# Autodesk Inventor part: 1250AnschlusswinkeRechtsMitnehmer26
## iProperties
Category: PARTsolutions
Created: 2011-08
Part Number: 1250AnschlusswinkeRechtsMitnehmer26
Catalog Web Link: www.cadenas.de
Description: 1250 Anschlusswinkel rechts Mitnehmer - Anschlusswinkel rechts Mitnehmer
Document SubType Name: Modeling
Designer: PARTsolutions
Density: 1 g/cm^3
Mass: 94.6561 g
Surface Area: 415.473 cm^2
Volume: 94.6561 cm^3
NB: 1250AnschlusswinkeRechtsMitnehmer26
NN: 1250 Anschlusswinkel rechts Mitnehmer
NT: Anschlusswinkel rechts Mitnehmer
NBSYN: 1250AnschlusswinkeRechtsMitnehmer26
LINA: 1250AnschlusswinkeRechtsMitnehmer26
BEST: 1250AnschlusswinkeRechtsMitnehmer
MA: 2
STEGV: 6
PIN: 18.800
KT: DUMMY
SUPPLIER: Kabelschlepp
ARTICLENO: 1250AnschlusswinkeRechtsMitnehmer26
BOMINFO: 1250AnschlusswinkeRechtsMitnehmer26
CREATOR: CADENAS GmbH
PSOL_IDENT_0: {\\10.0.0.251\ps_data\23d-libs\kabelschlepp\4_eketten_st\parts\1250_anschlusswinkel_rechts_m.prj},25
PSOL_IDENT_1: 1 {VTYP=3D},{NB=1250AnschlusswinkeRechtsMitnehmer26},{LINA=1250AnschlusswinkeRechtsMitnehmer26},{NN=
PSOL_IDENT_2: 1250 Anschlusswinkel rechts Mitnehmer},{DATE=31.05.2007 07:52:20},{GEOMDATE=20.03.2007 12:58:00},{VE
PSOL_IDENT_3: RSION=},{LINEID=10},{LINESUBID=-1},{WBVAR=MA,STEGV}  {NB=1250AnschlusswinkeRechtsMitnehmer26},{LINA=
PSOL_IDENT_4: 1250AnschlusswinkeRechtsMitnehmer26},{KT=DUMMY},{BEST=1250AnschlusswinkeRechtsMitnehmer},{MA=2},{STE
PSOL_IDENT_5: GV=6},{PIN=18.8}
Title: 1250AnschlusswinkeRechtsMitnehmer26
Author: Cadenas PARTsolutions
Comments: Anschlusswinkel rechts Mitnehmer
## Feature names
1. Extrusion1
2. Extrusion2
3. Extrusion3
4. Extrusion4
5. Extrusion5
6. Revolution1
7. Revolution2
8. Extrusion6
